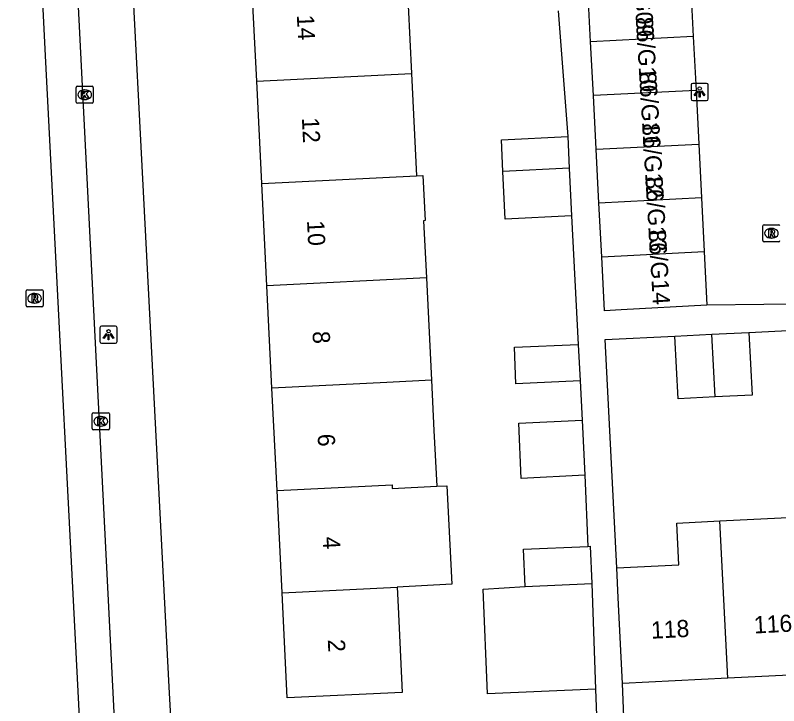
# Model space of a CAD drawing. Extents: x 161084 to 161928, y 385355 to 386522.
# Drawn here: x 161287.02 to 161331.43, y 385753.28 to 385793.45 of the extents above; entities that cross this region are included whole.
import ezdxf

# ---------------------------------------------------------------- set-up
doc = ezdxf.new("R2010")
doc.units = 0
for name, color, linetype in [('IMGEO_Kolk', 7, 'Continuous'), ('IMGEO_Lichtpunt', 7, 'Continuous'), ('IMGEO_Pand', 7, 'Continuous'), ('IMGEO_Pand_nummerreeks', 7, 'Continuous'), ('IMGEO_Rijbaan_lokaal_open', 7, 'Continuous'), ('IMGEO_Rioolput', 7, 'Continuous'), ('IMGEO_Voetpad_open', 7, 'Continuous')]:
    doc.layers.add(name, color=color, linetype=linetype)

msp = doc.modelspace()

# ---------------------------------------------------------------- linework, layer by layer
at = {"layer": 'IMGEO_Kolk'}
for p, q in [((161290.555, 385788.405), (161290.555, 385789.257)), ((161290.63, 385789.331), (161291.482, 385789.331)), ((161291.043, 385789.111), (161291.068, 385789.111)), ((161291.556, 385789.257), (161291.556, 385788.405)), ((161291.482, 385788.331), (161290.63, 385788.331)), ((161291.066, 385788.551), (161291.041, 385788.551)), ((161291.494, 385769.402), (161291.494, 385770.254)), ((161291.569, 385770.328), (161292.421, 385770.328)), ((161291.982, 385770.108), (161292.007, 385770.108)), ((161292.495, 385770.254), (161292.495, 385769.402)), ((161292.421, 385769.328), (161291.569, 385769.328)), ((161292.005, 385769.548), (161291.98, 385769.548))]:
    msp.add_line(p, q, dxfattribs=at)
for points in [[(161290.555, 385788.405), (161290.555, 385789.257)], [(161290.63, 385789.331), (161291.482, 385789.331)], [(161291.556, 385789.257), (161291.556, 385788.405)], [(161290.876, 385789.031), (161290.999, 385789.031), (161290.999, 385788.88), (161291.129, 385789.031), (161291.293, 385789.031), (161291.147, 385788.88), (161291.3, 385788.631), (161291.148, 385788.631), (161291.063, 385788.795), (161290.999, 385788.728), (161290.999, 385788.631), (161290.876, 385788.631), (161290.876, 385789.031)], [(161291.482, 385788.331), (161290.63, 385788.331)], [(161291.494, 385769.402), (161291.494, 385770.254)], [(161291.569, 385770.328), (161292.421, 385770.328)], [(161291.815, 385770.028), (161291.938, 385770.028), (161291.938, 385769.877), (161292.068, 385770.028), (161292.232, 385770.028), (161292.086, 385769.877), (161292.239, 385769.628), (161292.087, 385769.628), (161292.002, 385769.792), (161291.938, 385769.725), (161291.938, 385769.628), (161291.815, 385769.628), (161291.815, 385770.028)], [(161292.495, 385770.254), (161292.495, 385769.402)], [(161292.421, 385769.328), (161291.569, 385769.328)]]:
    msp.add_lwpolyline(points, dxfattribs=at)
for centre, start, end in [((161290.632, 385789.255), 91.552, 178.448), ((161290.632, 385789.255), 91.552, 178.448), ((161291.48, 385789.255), 1.552, 88.448), ((161291.48, 385789.255), 1.552, 88.448), ((161290.632, 385788.407), 181.552, 268.448), ((161290.632, 385788.407), 181.552, 268.448), ((161291.48, 385788.407), 271.552, 358.448), ((161291.48, 385788.407), 271.552, 358.448), ((161291.571, 385770.252), 91.552, 178.448), ((161291.571, 385770.252), 91.552, 178.448), ((161292.419, 385770.252), 1.552, 88.448), ((161292.419, 385770.252), 1.552, 88.448), ((161291.571, 385769.404), 181.552, 268.448), ((161291.571, 385769.404), 181.552, 268.448), ((161292.419, 385769.404), 271.552, 358.448), ((161292.419, 385769.404), 271.552, 358.448)]:
    msp.add_arc(centre, 0.0765, start, end, dxfattribs=at)
for centre, major_axis, ratio, start_param, end_param in [((161291.042, 385788.831), (-0.387, 0.002), 0.722429, 4.712389, 7.853982), ((161291.067, 385788.831), (-0.39, 0.002), 0.717154, 1.570796, 4.712389), ((161291.981, 385769.828), (-0.387, 0.002), 0.722429, 4.712389, 7.853982), ((161292.006, 385769.828), (-0.39, 0.002), 0.717154, 1.570796, 4.712389)]:
    msp.add_ellipse(centre, major_axis=major_axis, ratio=ratio, start_param=start_param, end_param=end_param, dxfattribs=at)
at = {"layer": 'IMGEO_Lichtpunt'}
for p, q in [((161326.333, 385789.396), (161326.333, 385788.589)), ((161326.333, 385789.396), (161326.333, 385788.589)), ((161327.235, 385789.491), (161326.427, 385789.491)), ((161327.235, 385789.491), (161326.427, 385789.491)), ((161327.329, 385788.589), (161327.329, 385789.396)), ((161327.329, 385788.589), (161327.329, 385789.396)), ((161326.427, 385788.495), (161327.235, 385788.495)), ((161326.427, 385788.495), (161327.235, 385788.495)), ((161292.847, 385775.367), (161292.039, 385775.367)), ((161292.847, 385775.367), (161292.039, 385775.367)), ((161291.945, 385775.272), (161291.945, 385774.465)), ((161291.945, 385775.272), (161291.945, 385774.465)), ((161292.941, 385774.465), (161292.941, 385775.272)), ((161292.941, 385774.465), (161292.941, 385775.272)), ((161292.039, 385774.371), (161292.847, 385774.371)), ((161292.039, 385774.371), (161292.847, 385774.371))]:
    msp.add_line(p, q, dxfattribs=at)
for points in [[(161326.707, 385789.06), (161326.746, 385789.032), (161326.558, 385788.77), (161326.52, 385788.797), (161326.707, 385789.06)], [(161326.809, 385789.012), (161326.856, 385789.012), (161326.856, 385788.69), (161326.809, 385788.69), (161326.809, 385789.012)], [(161326.919, 385789.032), (161326.957, 385789.059), (161327.144, 385788.797), (161327.105, 385788.769), (161326.919, 385789.032)], [(161292.319, 385774.936), (161292.358, 385774.908), (161292.17, 385774.646), (161292.132, 385774.673), (161292.319, 385774.936)], [(161292.531, 385774.908), (161292.569, 385774.935), (161292.756, 385774.673), (161292.717, 385774.645), (161292.531, 385774.908)], [(161292.421, 385774.888), (161292.468, 385774.888), (161292.468, 385774.566), (161292.421, 385774.566), (161292.421, 385774.888)]]:
    msp.add_lwpolyline(points, dxfattribs=at)
for centre in [(161326.832, 385789.194), (161292.444, 385775.07)]:
    msp.add_circle(centre, 0.0994, dxfattribs=at)
for centre, start, end in [((161326.427, 385789.396), 90, 180), ((161326.427, 385789.396), 90, 180), ((161327.235, 385789.396), 0, 90), ((161327.235, 385789.396), 0, 90), ((161326.427, 385788.589), 180, 270), ((161326.427, 385788.589), 180, 270), ((161327.235, 385788.589), 270, 0), ((161327.235, 385788.589), 270, 360), ((161292.039, 385775.272), 90, 180), ((161292.039, 385775.272), 90, 180), ((161292.847, 385775.272), 0, 90), ((161292.847, 385775.272), 0, 90), ((161292.039, 385774.465), 180, 270), ((161292.039, 385774.465), 180, 270), ((161292.847, 385774.465), 270, 0), ((161292.847, 385774.465), 270, 360)]:
    msp.add_arc(centre, 0.0946, start, end, dxfattribs=at)
at = {"layer": 'IMGEO_Pand'}
for points in [[(161309.774, 385796.01), (161310.068, 385790.058)], [(161301.063, 385789.612), (161300.769, 385795.563)], [(161326.303, 385795.334), (161326.462, 385792.208)], [(161320.49, 385791.904), (161320.328, 385795.03)], [(161326.462, 385792.208), (161320.49, 385791.904)], [(161320.651, 385788.778), (161320.49, 385791.904)], [(161326.462, 385792.208), (161326.621, 385789.082)], [(161301.063, 385789.612), (161310.068, 385790.058)], [(161310.068, 385790.058), (161310.363, 385784.107)], [(161301.359, 385783.66), (161301.063, 385789.612)], [(161326.621, 385789.082), (161320.651, 385788.778)], [(161320.812, 385785.653), (161320.651, 385788.778)], [(161326.621, 385789.082), (161326.78, 385785.956)], [(161315.382, 385784.356), (161315.296, 385786.213), (161319.165, 385786.393)], [(161319.165, 385786.393), (161319.251, 385784.548)], [(161320.812, 385785.653), (161326.78, 385785.956)], [(161320.973, 385782.527), (161320.812, 385785.653)], [(161326.78, 385785.956), (161326.939, 385782.83)], [(161319.251, 385784.548), (161315.382, 385784.356)], [(161319.38, 385781.774), (161315.511, 385781.594), (161315.382, 385784.356)], [(161319.251, 385784.548), (161319.38, 385781.774)], [(161301.359, 385783.66), (161310.363, 385784.107)], [(161310.363, 385784.107), (161310.736, 385784.125), (161310.866, 385781.506), (161310.769, 385781.501), (161310.934, 385778.168)], [(161301.654, 385777.708), (161301.359, 385783.66)], [(161326.939, 385782.83), (161320.973, 385782.527)], [(161321.134, 385779.401), (161320.973, 385782.527)], [(161326.939, 385782.83), (161327.098, 385779.704)], [(161321.134, 385779.401), (161327.098, 385779.704)], [(161327.257, 385776.578), (161322.265, 385776.309), (161321.296, 385776.257), (161321.134, 385779.401)], [(161327.098, 385779.704), (161327.257, 385776.578)], [(161310.934, 385778.168), (161301.654, 385777.708)], [(161310.934, 385778.168), (161311.228, 385772.216)], [(161301.949, 385771.756), (161301.654, 385777.708)], [(161327.538, 385774.893), (161329.695, 385775.002)], [(161329.695, 385775.002), (161329.892, 385771.357), (161327.734, 385771.248)], [(161325.381, 385774.784), (161327.538, 385774.893)], [(161327.734, 385771.248), (161325.577, 385771.14), (161325.381, 385774.784)], [(161327.734, 385771.248), (161327.538, 385774.893)], [(161319.885, 385772.176), (161316.146, 385772.011), (161316.052, 385774.139), (161319.773, 385774.298)], [(161319.773, 385774.298), (161319.885, 385772.176)], [(161311.228, 385772.216), (161308.64, 385772.088), (161301.949, 385771.756)], [(161311.228, 385772.216), (161311.373, 385769.284), (161311.534, 385766.051)], [(161302.244, 385765.805), (161301.949, 385771.756)], [(161320.146, 385766.693), (161316.454, 385766.51), (161316.312, 385769.727), (161320.005, 385769.89)], [(161320.005, 385769.89), (161320.146, 385766.693)], [(161302.244, 385765.805), (161308.935, 385766.137), (161308.946, 385765.923), (161311.534, 385766.051)], [(161311.534, 385766.051), (161312.129, 385766.081), (161312.414, 385760.343), (161309.23, 385760.185)], [(161302.539, 385759.853), (161302.244, 385765.805)], [(161328.01, 385764.034), (161333.958, 385764.335)], [(161322.012, 385761.297), (161325.625, 385761.48), (161325.502, 385763.907), (161328.01, 385764.034)], [(161328.473, 385754.879), (161328.01, 385764.034)], [(161316.673, 385760.224), (161316.577, 385762.385), (161320.329, 385762.552)], [(161320.329, 385762.552), (161320.46, 385762.558), (161320.556, 385760.397)], [(161322.352, 385754.569), (161322.1, 385759.563), (161322.012, 385761.297)], [(161316.673, 385760.224), (161320.556, 385760.397)], [(161320.556, 385760.397), (161320.777, 385754.248)], [(161309.23, 385760.185), (161309.287, 385759.041), (161309.535, 385754.047), (161302.842, 385753.731), (161302.539, 385759.853)], [(161302.539, 385759.853), (161309.23, 385760.185)], [(161320.777, 385754.248), (161314.5, 385753.978), (161314.238, 385760.065), (161316.673, 385760.224)], [(161334.421, 385755.18), (161328.473, 385754.879)], [(161328.473, 385754.879), (161322.352, 385754.569)]]:
    msp.add_lwpolyline(points, dxfattribs=at)
at = {"layer": 'IMGEO_Rijbaan_lokaal_open'}
for points in [[(161289.05, 385826.037), (161287.016, 385825.999), (161287.098, 385824.82), (161287.218, 385821.238), (161287.484, 385816.036), (161287.661, 385812.59), (161287.944, 385807.065), (161288.2, 385802.078), (161288.462, 385796.968), (161288.743, 385791.485), (161290.968, 385748.079), (161293.511, 385748.193)], [(161337.206, 385776.693), (161327.257, 385776.578)]]:
    msp.add_lwpolyline(points, dxfattribs=at)
at = {"layer": 'IMGEO_Rioolput'}
for p, q in [((161330.506, 385780.342), (161330.506, 385781.194)), ((161330.581, 385781.268), (161331.433, 385781.268)), ((161330.994, 385781.048), (161331.019, 385781.048)), ((161331.433, 385780.268), (161330.581, 385780.268)), ((161331.017, 385780.488), (161330.992, 385780.488)), ((161287.643, 385776.559), (161287.643, 385777.411)), ((161287.718, 385777.485), (161288.57, 385777.485)), ((161288.131, 385777.265), (161288.156, 385777.265)), ((161288.644, 385777.411), (161288.644, 385776.559)), ((161288.154, 385776.705), (161288.129, 385776.705)), ((161288.57, 385776.485), (161287.718, 385776.485))]:
    msp.add_line(p, q, dxfattribs=at)
for points in [[(161330.506, 385780.342), (161330.506, 385781.194)], [(161330.581, 385781.268), (161331.433, 385781.268)], [(161331.095, 385780.966), (161330.843, 385780.968), (161330.843, 385780.568)], [(161330.843, 385780.568), (161330.967, 385780.568), (161330.967, 385780.73), (161330.978, 385780.73)], [(161331.021, 385780.887), (161330.967, 385780.887), (161330.967, 385780.806)], [(161330.967, 385780.806), (161331.019, 385780.806)], [(161331.025, 385780.701), (161331.096, 385780.568), (161331.236, 385780.568), (161331.171, 385780.694)], [(161331.433, 385780.268), (161330.581, 385780.268)], [(161287.643, 385776.559), (161287.643, 385777.411)], [(161287.718, 385777.485), (161288.57, 385777.485)], [(161288.232, 385777.183), (161287.98, 385777.185), (161287.98, 385776.785)], [(161288.644, 385777.411), (161288.644, 385776.559)], [(161287.98, 385776.785), (161288.104, 385776.785), (161288.104, 385776.947), (161288.115, 385776.947)], [(161288.158, 385777.104), (161288.104, 385777.104), (161288.104, 385777.023)], [(161288.104, 385777.023), (161288.156, 385777.023)], [(161288.162, 385776.918), (161288.233, 385776.785), (161288.373, 385776.785), (161288.308, 385776.911)], [(161288.57, 385776.485), (161287.718, 385776.485)]]:
    msp.add_lwpolyline(points, dxfattribs=at)
for centre, radius, start, end in [((161330.583, 385781.192), 0.0765, 91.552, 178.448), ((161330.583, 385781.192), 0.0765, 91.552, 178.448), ((161331.431, 385781.192), 0.0765, 1.552, 88.448), ((161331.431, 385781.192), 0.0765, 1.552, 88.448), ((161330.977, 385780.677), 0.0533, 26.0293, 88.6989), ((161331.003, 385780.995), 0.19, 274.7715, 282.9687), ((161331.027, 385780.791), 0.0964, 77.0061, 93.1865), ((161331.041, 385780.848), 0.0378, 276.6634, 79.6772), ((161331.094, 385780.856), 0.109, 350.3612, 89.416), ((161331.092, 385780.856), 0.112, 277.5842, 350.9817), ((161331.076, 385780.641), 0.108, 29.5134, 73.7905), ((161330.583, 385780.344), 0.0765, 181.552, 268.448), ((161330.583, 385780.344), 0.0765, 181.552, 268.448), ((161331.431, 385780.344), 0.0765, 271.552, 358.448), ((161331.431, 385780.344), 0.0765, 271.552, 358.448), ((161287.72, 385777.409), 0.0765, 91.552, 178.448), ((161287.72, 385777.409), 0.0765, 91.552, 178.448), ((161288.231, 385777.073), 0.109, 350.3612, 89.416), ((161288.568, 385777.409), 0.0765, 1.552, 88.448), ((161288.568, 385777.409), 0.0765, 1.552, 88.448), ((161288.114, 385776.894), 0.0533, 26.0293, 88.6989), ((161288.14, 385777.212), 0.19, 274.7715, 282.9687), ((161288.164, 385777.008), 0.0964, 77.0061, 93.1865), ((161288.178, 385777.065), 0.0378, 276.6634, 79.6772), ((161288.229, 385777.073), 0.112, 277.5842, 350.9817), ((161288.213, 385776.858), 0.108, 29.5134, 73.7905), ((161287.72, 385776.561), 0.0765, 181.552, 268.448), ((161287.72, 385776.561), 0.0765, 181.552, 268.448), ((161288.568, 385776.561), 0.0765, 271.552, 358.448), ((161288.568, 385776.561), 0.0765, 271.552, 358.448)]:
    msp.add_arc(centre, radius, start, end, dxfattribs=at)
for centre, major_axis, ratio, start_param, end_param in [((161330.993, 385780.768), (-0.387, 0.002), 0.722429, 4.712389, 7.853982), ((161331.018, 385780.768), (-0.39, 0.002), 0.717154, 1.570796, 4.712389), ((161288.13, 385776.985), (-0.387, 0.002), 0.722429, 4.712389, 7.853982), ((161288.155, 385776.985), (-0.39, 0.002), 0.717154, 1.570796, 4.712389)]:
    msp.add_ellipse(centre, major_axis=major_axis, ratio=ratio, start_param=start_param, end_param=end_param, dxfattribs=at)
at = {"layer": 'IMGEO_Voetpad_open'}
for points in [[(161292.885, 385750.57), (161290.358, 385800.504), (161289.05, 385826.037)], [(161292.285, 385825.118), (161295.952, 385754.37), (161296.116, 385751.21), (161296.554, 385750), (161296.707, 385749.779), (161296.879, 385749.572), (161297.069, 385749.382), (161297.276, 385749.21), (161297.497, 385749.056), (161297.73, 385748.923), (161297.975, 385748.811), (161298.228, 385748.722), (161298.489, 385748.656), (161298.755, 385748.613), (161299.023, 385748.594), (161299.076, 385748.593)], [(161318.592, 385793.711), (161319.165, 385786.393)], [(161319.38, 385781.774), (161319.773, 385774.298)], [(161329.695, 385775.002), (161337.296, 385775.386)], [(161322.012, 385761.297), (161321.338, 385774.58), (161325.381, 385774.784)], [(161319.885, 385772.176), (161320.005, 385769.89)], [(161320.146, 385766.693), (161320.329, 385762.552)], [(161322.529, 385749.751), (161322.352, 385754.569)], [(161320.777, 385754.248), (161320.944, 385749.672)]]:
    msp.add_lwpolyline(points, dxfattribs=at)

# ---------------------------------------------------------------- texts
at = {"layer": 'IMGEO_Pand_nummerreeks'}
for s, rotation, p in [('86/G09', 273.4391, (161322.921, 385796.525)), ('14', 272.8376, (161303.396, 385793.462)), ('86/G10', 273.4391, (161323.113, 385793.333)), ('86/G11', 273.4391, (161323.306, 385790.131)), ('12', 272.8376, (161303.691, 385787.484)), ('86/G12', 273.4391, (161323.485, 385787.152)), ('86/G13', 273.4391, (161323.671, 385784.05)), ('10', 272.8376, (161303.989, 385781.498)), ('86/G14', 273.4391, (161323.857, 385780.955)), ('8', 272.8376, (161304.308, 385775.057)), ('6', 272.8359, (161304.603, 385769.081)), ('4', 272.8359, (161304.9, 385763.101)), ('116', 2.8986, (161330.01, 385757.48)), ('118', 2.8986, (161324.026, 385757.177)), ('2', 272.8376, (161305.196, 385757.123))]:
    msp.add_text(s, height=1, rotation=rotation, dxfattribs=at).set_placement(p)

doc.saveas('drawing.dxf')
